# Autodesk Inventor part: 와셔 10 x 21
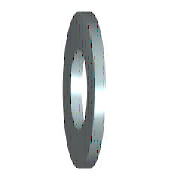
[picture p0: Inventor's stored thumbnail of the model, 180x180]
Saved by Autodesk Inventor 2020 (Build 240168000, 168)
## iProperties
Created: 2012-02
Part Number: 와셔 10 x 21
Material: 강철, 연강
Description: 평면 와셔
Document SubType Name: Modeling
Standard: KS B 1326
Designer: mduedu
Standards Organization: KS
Language: ko-KR
Size Designation: 10x21
Categories: <MemberInstance><Categories><Category DisplayName="조임쇠" InternalName="e4da775c-781d-43d5-af7c-5136215cf5a6" Mnemonic="FSTN"><Category DisplayName="와셔" InternalN
Density: 1 g/cm^3
Appearance: 파란색 - 벽 페인트 - 광택
IsCustomPart: 1
Author: mduedu
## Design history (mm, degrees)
sketch "스케치"
  geometry: C1 r 10.5 at (0, 0); C2 r 5.25 at (0, 0); 1 further point
  constraints: 2 centre point, 2 coincident
  dimensions: "d0" = 10.5 diameter of C2 (= SD1); "d1" = 21 diameter of C1 (= SD2)
extrude "본체" new body sketch "스케치" distance "d2" = 2 (= SD); taper "d3" = 0 deg
workaxis "Work Axis1"
workplane "Work Plane1"
body "Solid1"
other parameters: "SD1" = 10.5 [user parameter; used in 1 equation term], "SD2" = 21 [user parameter; used in 1 equation term], "SD" = 2 [user parameter; used in 1 equation term], "d4" = 0, "d5" = 0, "d6" = 0, "d7" = 0
